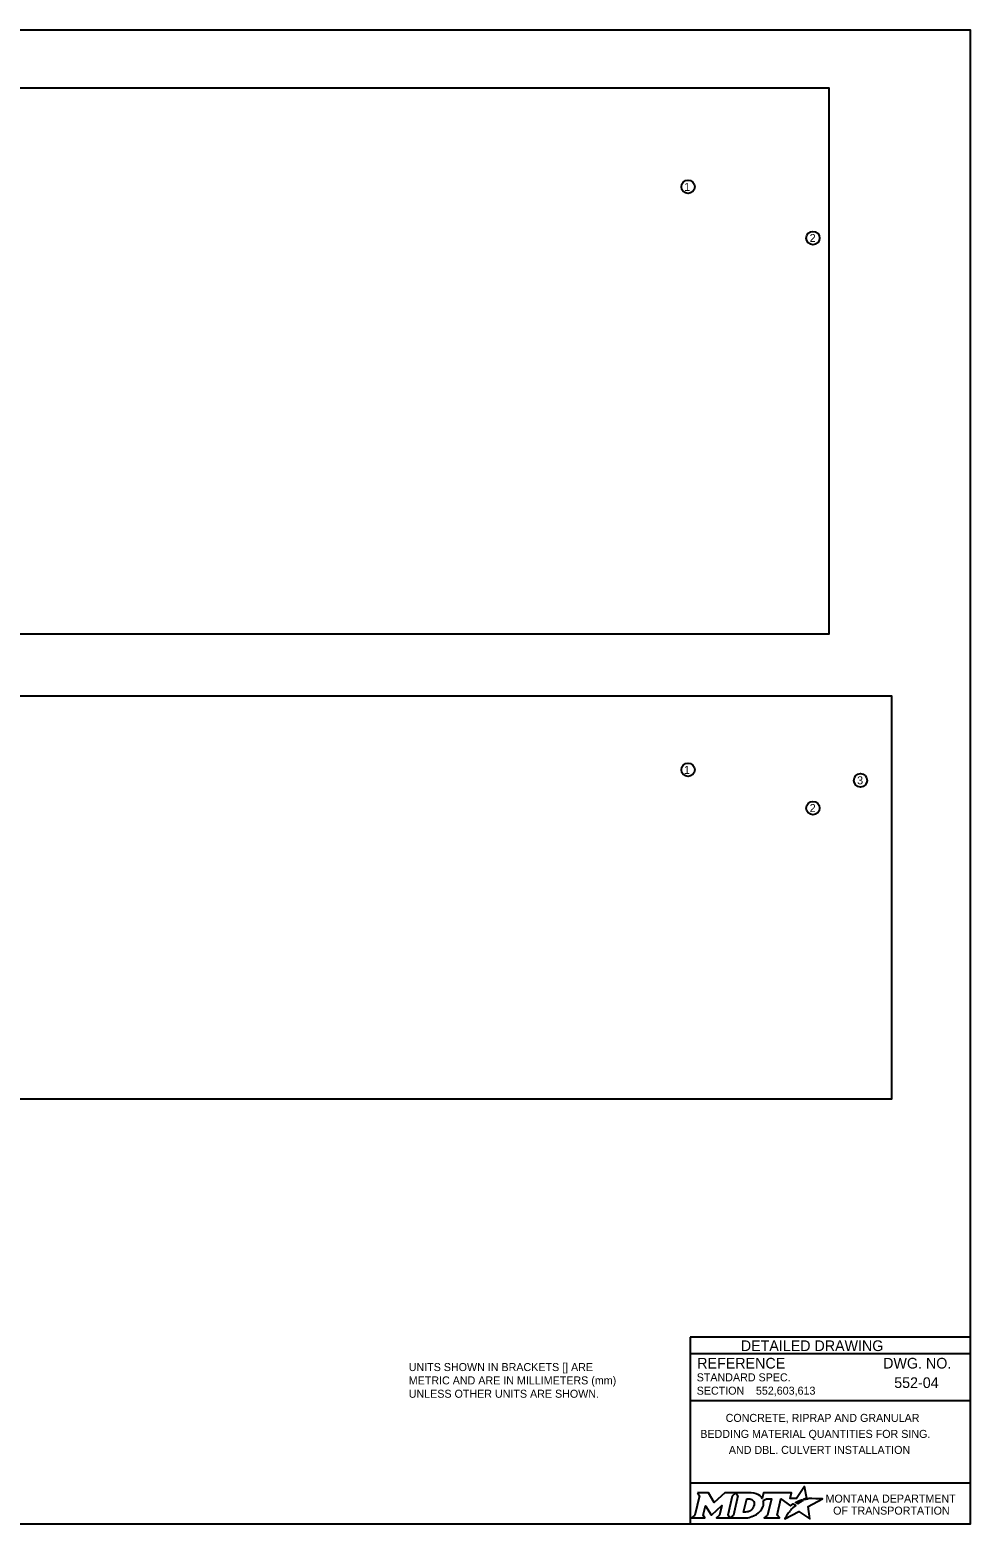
# Model space of a CAD drawing. Extents: x 49991.4 to 50021, y 49987.6 to 50011.4.
# Drawn here: x 50009.7 to 50016.75, y 49987.8 to 49999 of the extents above; entities that cross this region are included whole.
import ezdxf

# ---------------------------------------------------------------- set-up
doc = ezdxf.new("R2010")
doc.units = 0
for name, color, linetype in [('Default', 7, 'Continuous'), ('Level 1', 7, 'Continuous'), ('Level 2', 7, 'Continuous'), ('Level 5', 7, 'Continuous')]:
    doc.layers.add(name, color=color, linetype=linetype)

msp = doc.modelspace()

# ---------------------------------------------------------------- linework, layer by layer
at = {"layer": 'Default'}
for points in [[(50015.513, 49987.981), (50015.502, 49987.987), (50015.514, 49987.99), (50015.526, 49987.991), (50015.508, 49988.082), (50015.449, 49987.99), (50015.401, 49987.99), (50015.412, 49988.034), (50015.202, 49988.034), (50015.192, 49987.991), (50015.186, 49988)], [(50014.706, 49988.034), (50014.72, 49988.01), (50014.686, 49987.867), (50014.66, 49987.845), (50014.762, 49987.845), (50014.749, 49987.867), (50014.765, 49987.937), (50014.809, 49987.868), (50014.814, 49987.868), (50014.889, 49987.938), (50014.872, 49987.867), (50014.848, 49987.845), (50014.949, 49987.845), (50014.936, 49987.868), (50014.969, 49988.011)], [(50014.969, 49988.011), (50014.994, 49988.034), (50014.912, 49988.034), (50014.832, 49987.961), (50014.788, 49988.034), (50014.706, 49988.034)], [(50015.108, 49988.034), (50014.994, 49988.034), (50015.009, 49988.011), (50014.975, 49987.867), (50014.949, 49987.845), (50015.06, 49987.845)], [(50015.132, 49987.947), (50015.13, 49987.939), (50015.127, 49987.93), (50015.123, 49987.922), (50015.118, 49987.914), (50015.111, 49987.907), (50015.103, 49987.901), (50015.095, 49987.896), (50015.086, 49987.892), (50015.077, 49987.89), (50015.067, 49987.889), (50015.052, 49987.889), (50015.075, 49987.989), (50015.091, 49987.989), (50015.099, 49987.988), (50015.106, 49987.986), (50015.113, 49987.983), (50015.119, 49987.979), (50015.124, 49987.974), (50015.128, 49987.968), (50015.13, 49987.962), (50015.132, 49987.955), (50015.132, 49987.952), (50015.132, 49987.947)], [(50015.199, 49987.975), (50015.224, 49987.988), (50015.261, 49987.988), (50015.232, 49987.867), (50015.205, 49987.845), (50015.321, 49987.845), (50015.304, 49987.867), (50015.332, 49987.988), (50015.403, 49987.936), (50015.424, 49987.951), (50015.444, 49987.94)], [(50015.388, 49987.884), (50015.373, 49987.86), (50015.368, 49987.852), (50015.362, 49987.844), (50015.36, 49987.839), (50015.465, 49987.893), (50015.549, 49987.838), (50015.536, 49987.93), (50015.643, 49987.989), (50015.594, 49987.989), (50015.564, 49987.99), (50015.543, 49987.99), (50015.536, 49987.989), (50015.531, 49987.987), (50015.523, 49987.985), (50015.513, 49987.981)], [(50015.462, 49987.954), (50015.46, 49987.952), (50015.442, 49987.961), (50015.452, 49987.967), (50015.456, 49987.969), (50015.465, 49987.973), (50015.47, 49987.976), (50015.478, 49987.979), (50015.485, 49987.982), (50015.497, 49987.974), (50015.493, 49987.972), (50015.489, 49987.97), (50015.484, 49987.967), (50015.479, 49987.965), (50015.478, 49987.963), (50015.475, 49987.962), (50015.472, 49987.96), (50015.47, 49987.959), (50015.467, 49987.957), (50015.465, 49987.955), (50015.462, 49987.954)], [(50015.106, 49987.852), (50015.114, 49987.855), (50015.127, 49987.86), (50015.148, 49987.871)], [(50015.402, 49987.9), (50015.402, 49987.9)]]:
    msp.add_lwpolyline(points, dxfattribs=at)
for centre, radius, start, end in [((50015.131, 49987.955), 0.0709, 339.5329, 15.8582), ((50015.087, 49987.973), 0.118, 300.9103, 339.1383)]:
    msp.add_arc(centre, radius, start, end, dxfattribs=at)
for centre, major_axis, ratio, start_param, end_param in [((50015.106, 49987.986), (0.0834, -0.0037), 0.568097, 0.61298, 1.570796), ((50015.161, 49987.994), (0.0361, -0.0295), 0.469099, 1.225588, 1.570796), ((50015.06, 49987.993), (0, 0.148), 0.987302, 3.139398, 3.456847), ((50015.395, 49987.892), (-0.00694, -0.00806), 0.008222, 0, 3.137361), ((50015.412, 49987.911), (-0.0098, -0.0102), 0.016458, 3.141593, 6.279097), ((50015.433, 49987.93), (-0.0112, -0.0097), 0.021651, 3.157348, 6.283185)]:
    msp.add_ellipse(centre, major_axis=major_axis, ratio=ratio, start_param=start_param, end_param=end_param, dxfattribs=at)
at = {"layer": 'Level 1'}
msp.add_lwpolyline([(49999.384, 49998.999), (50016.75, 49998.999), (50016.75, 49987.799), (49999.384, 49987.799)], close=True, dxfattribs=at)
at = {"layer": 'Level 2'}
for points in [[(50008.867, 49994.472), (50015.693, 49994.472), (50015.693, 49998.563), (50008.867, 49998.563)], [(50008.87, 49990.986), (50016.162, 49990.986), (50016.162, 49994.006), (50008.87, 49994.006)]]:
    msp.add_lwpolyline(points, close=True, dxfattribs=at)
for centre in [(50014.635, 49997.823), (50015.572, 49997.439), (50014.635, 49993.453), (50015.928, 49993.374), (50015.572, 49993.166)]:
    msp.add_circle(centre, 0.05, dxfattribs=at)
at = {"layer": 'Level 5'}
for p, q in [((50016.75, 49989.199), (50014.65, 49989.199)), ((50014.65, 49989.199), (50014.65, 49987.799)), ((50016.75, 49989.074), (50014.65, 49989.074)), ((50016.386, 49988.859), (50016.386, 49988.859)), ((50015.144, 49988.799), (50015.144, 49988.799)), ((50016.75, 49988.724), (50014.65, 49988.724)), ((50015.7, 49988.475), (50015.7, 49988.475)), ((50016.75, 49988.106), (50014.65, 49988.106))]:
    msp.add_line(p, q, dxfattribs=at)

# ---------------------------------------------------------------- texts
at = {"layer": 'Default'}
for s, p in [('MONTANA DEPARTMENT', (50015.666, 49987.96)), ('OF TRANSPORTATION', (50015.723, 49987.87))]:
    msp.add_text(s, height=0.06, dxfattribs=at).set_placement(p)
at = {"layer": 'Level 2'}
for s, height, p in [('1', 0.06, (50014.606, 49997.792)), ('2', 0.06, (50015.547, 49997.409)), ('1', 0.06, (50014.604, 49993.422)), ('3', 0.06, (50015.903, 49993.344)), ('2', 0.06, (50015.547, 49993.136)), ('UNITS SHOWN IN BRACKETS [] ARE ', 0.06, (50012.541, 49988.946)), ('METRIC AND ARE IN MILLIMETERS (mm) ', 0.06, (50012.541, 49988.846)), ('552-04', 0.08, (50016.181, 49988.819)), ('UNLESS OTHER UNITS ARE SHOWN.', 0.06, (50012.541, 49988.746)), ('552,603,613', 0.06, (50015.144, 49988.769)), ('CONCRETE, RIPRAP AND GRANULAR', 0.06, (50014.917, 49988.565)), ('BEDDING MATERIAL QUANTITIES FOR SING.', 0.06, (50014.727, 49988.445)), ('AND DBL. CULVERT INSTALLATION', 0.06, (50014.941, 49988.325))]:
    msp.add_text(s, height=height, dxfattribs=at).set_placement(p)
at = {"layer": 'Level 5'}
for s, height, p in [('DETAILED DRAWING', 0.0799, (50015.031, 49989.096)), ('REFERENCE', 0.08, (50014.704, 49988.965)), ('DWG. NO.', 0.08, (50016.098, 49988.965)), ('STANDARD SPEC.', 0.06, (50014.7, 49988.869)), ('SECTION', 0.06, (50014.7, 49988.769))]:
    msp.add_text(s, height=height, dxfattribs=at).set_placement(p)

doc.saveas('drawing.dxf')
